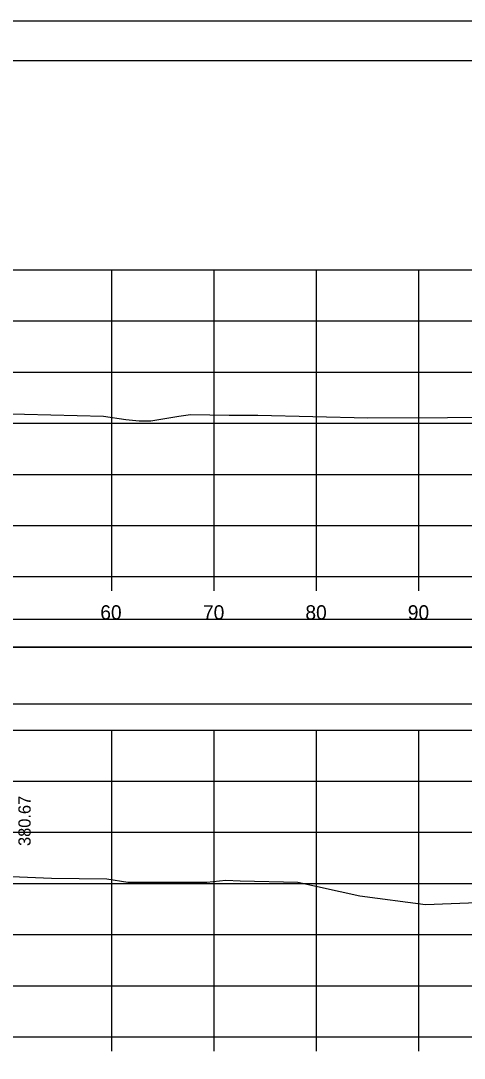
# Model space of a CAD drawing. Extents: x -37291014 to -37290680, y -936053 to -933067.
# Drawn here: x -37290792 to -37290748.7, y -933808 to -933706.6 of the extents above; entities that cross this region are included whole.
import ezdxf

# ---------------------------------------------------------------- set-up
doc = ezdxf.new("R2010")
doc.units = 0
for name, color, linetype in [('Default', 7, 'Continuous'), ('R_Axis', 7, 'Continuous'), ('R_Axis Annot', 7, 'Continuous'), ('R_Border', 7, 'Continuous'), ('R_Exist Surface', 7, 'Continuous'), ('R_Grid', 7, 'Continuous'), ('R_No Plot', 7, 'Continuous'), ('R_Xsect Elev', 7, 'Continuous')]:
    doc.layers.add(name, color=color, linetype=linetype)

msp = doc.modelspace()

# ---------------------------------------------------------------- linework, layer by layer
at = {"layer": 'Default'}
for points in [[(-37290992.48, -933767.85), (-37290693.72, -933767.85), (-37290693.72, -933765.14), (-37290992.48, -933765.14)], [(-37290992.71, -933773.37), (-37290693.95, -933773.37), (-37290693.95, -933767.85), (-37290992.71, -933767.85)]]:
    msp.add_lwpolyline(points, close=True, dxfattribs=at)
at = {"layer": 'R_Axis'}
for p, q in [((-37290993.1, -933760.94), (-37290693.1, -933760.94)), ((-37290783.1, -933762.34), (-37290783.1, -933760.94)), ((-37290773.1, -933762.34), (-37290773.1, -933760.94)), ((-37290763.1, -933762.34), (-37290763.1, -933760.94)), ((-37290753.1, -933762.34), (-37290753.1, -933760.94)), ((-37290993.1, -933805.94), (-37290693.1, -933805.94)), ((-37290783.1, -933807.34), (-37290783.1, -933805.94)), ((-37290773.1, -933807.34), (-37290773.1, -933805.94)), ((-37290763.1, -933807.34), (-37290763.1, -933805.94)), ((-37290753.1, -933807.34), (-37290753.1, -933805.94))]:
    msp.add_line(p, q, dxfattribs=at)
at = {"layer": 'R_Border'}
msp.add_line((-37291001.1, -933710.48), (-37290684.92, -933710.48), dxfattribs=at)
at = {"layer": 'R_Exist Surface'}
for points in [[(-37290809.01, -933744.64), (-37290791.62, -933745.06), (-37290783.9, -933745.24), (-37290781.71, -933745.58), (-37290780.41, -933745.72), (-37290779.81, -933745.71), (-37290779.29, -933745.7), (-37290776.55, -933745.25), (-37290775.42, -933745.1), (-37290771.64, -933745.14), (-37290768.85, -933745.15), (-37290758.1, -933745.42), (-37290742.52, -933745.35), (-37290738.21, -933745.38), (-37290736.93, -933745.38), (-37290734.07, -933745.43), (-37290732.13, -933746.2), (-37290729.01, -933747.46), (-37290722.73, -933747.38), (-37290715.31, -933747.17), (-37290705.54, -933747.2), (-37290699.03, -933747.19), (-37290693.1, -933747.12)], [(-37290794.5, -933790.19), (-37290788.98, -933790.44), (-37290783.59, -933790.5), (-37290781.54, -933790.82), (-37290780.99, -933790.81), (-37290773.83, -933790.81), (-37290771.97, -933790.63), (-37290770.55, -933790.68), (-37290764.94, -933790.82), (-37290758.87, -933792.16), (-37290752.47, -933793), (-37290739.91, -933792.52), (-37290736.45, -933792.48), (-37290727.22, -933792.37), (-37290720.37, -933792.42), (-37290711.07, -933792.44), (-37290702.14, -933792.36), (-37290693.1, -933792.26)]]:
    msp.add_lwpolyline(points, dxfattribs=at)
at = {"layer": 'R_Grid'}
for p, q in [((-37290993.1, -933730.94), (-37290693.1, -933730.94)), ((-37290783.1, -933760.94), (-37290783.1, -933730.94)), ((-37290773.1, -933760.94), (-37290773.1, -933730.94)), ((-37290763.1, -933760.94), (-37290763.1, -933730.94)), ((-37290753.1, -933760.94), (-37290753.1, -933730.94)), ((-37290993.1, -933735.94), (-37290693.1, -933735.94)), ((-37290993.1, -933740.94), (-37290693.1, -933740.94)), ((-37290993.1, -933745.94), (-37290693.1, -933745.94)), ((-37290993.1, -933750.94), (-37290693.1, -933750.94)), ((-37290993.1, -933755.94), (-37290693.1, -933755.94)), ((-37290993.1, -933760.94), (-37290693.1, -933760.94)), ((-37290993.1, -933775.94), (-37290693.1, -933775.94)), ((-37290783.1, -933805.94), (-37290783.1, -933775.94)), ((-37290773.1, -933805.94), (-37290773.1, -933775.94)), ((-37290763.1, -933805.94), (-37290763.1, -933775.94)), ((-37290753.1, -933805.94), (-37290753.1, -933775.94)), ((-37290993.1, -933780.94), (-37290693.1, -933780.94)), ((-37290993.1, -933785.94), (-37290693.1, -933785.94)), ((-37290993.1, -933790.94), (-37290693.1, -933790.94)), ((-37290993.1, -933795.94), (-37290693.1, -933795.94)), ((-37290993.1, -933800.94), (-37290693.1, -933800.94)), ((-37290993.1, -933805.94), (-37290693.1, -933805.94))]:
    msp.add_line(p, q, dxfattribs=at)
at = {"layer": 'R_No Plot'}
msp.add_line((-37291013.5, -933706.59), (-37290680.17, -933706.59), dxfattribs=at)
for points in [[(-37291013.51, -933706.59), (-37290680.17, -933706.59), (-37290680.17, -933919.93), (-37291013.51, -933919.93)], [(-37290767.18, -933710.48), (-37290747.56, -933710.48), (-37290747.56, -933720.36), (-37290731.45, -933720.36), (-37290708.25, -933720.36), (-37290708.25, -933744.7), (-37290684.92, -933744.7), (-37290684.92, -933915.94), (-37291001.1, -933915.94), (-37291001.1, -933710.48)]]:
    msp.add_lwpolyline(points, close=True, dxfattribs=at)

# ---------------------------------------------------------------- texts
at = {"layer": 'R_Axis Annot'}
for s, p in [('60', (-37290784.22, -933765.14)), ('70', (-37290774.19, -933765.14)), ('80', (-37290764.19, -933765.14)), ('90', (-37290754.19, -933765.14))]:
    msp.add_text(s, height=1.4, dxfattribs=at).set_placement(p)
at = {"layer": 'R_Xsect Elev'}
msp.add_text('380.67', height=1.2, rotation=90, dxfattribs=at).set_placement((-37290791.02, -933787.28))

doc.saveas('drawing.dxf')
